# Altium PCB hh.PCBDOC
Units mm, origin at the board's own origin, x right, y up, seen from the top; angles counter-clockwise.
Board outline 200 x 200 mm, 4 copper layers (Top Layer, Internal Plane 1, Internal Plane 2, Bottom Layer); 47 components, 0 nets, 248 pads, 0 vias.
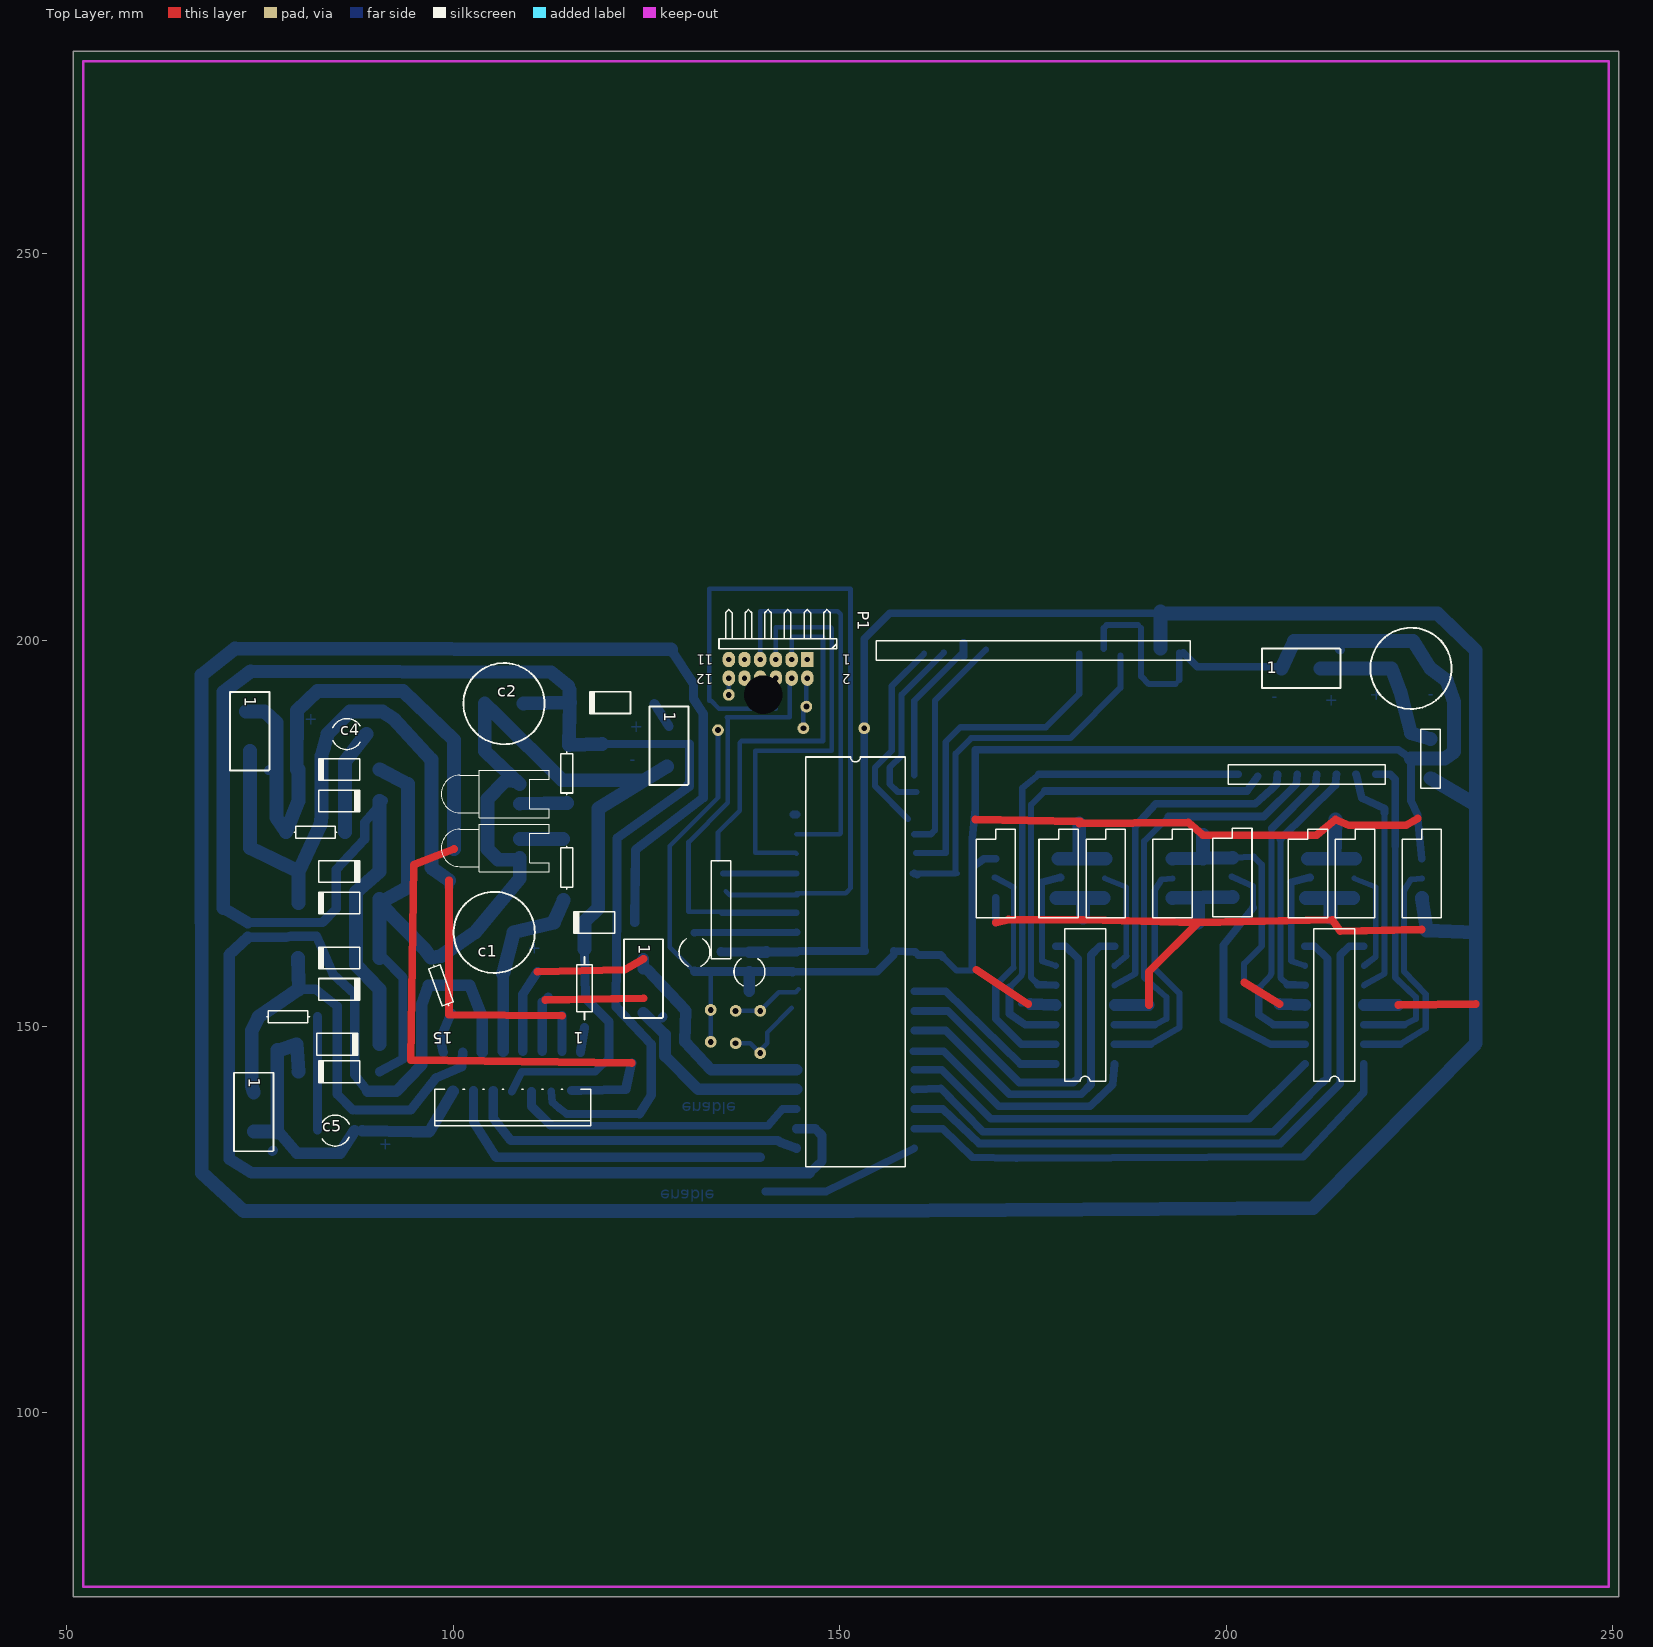
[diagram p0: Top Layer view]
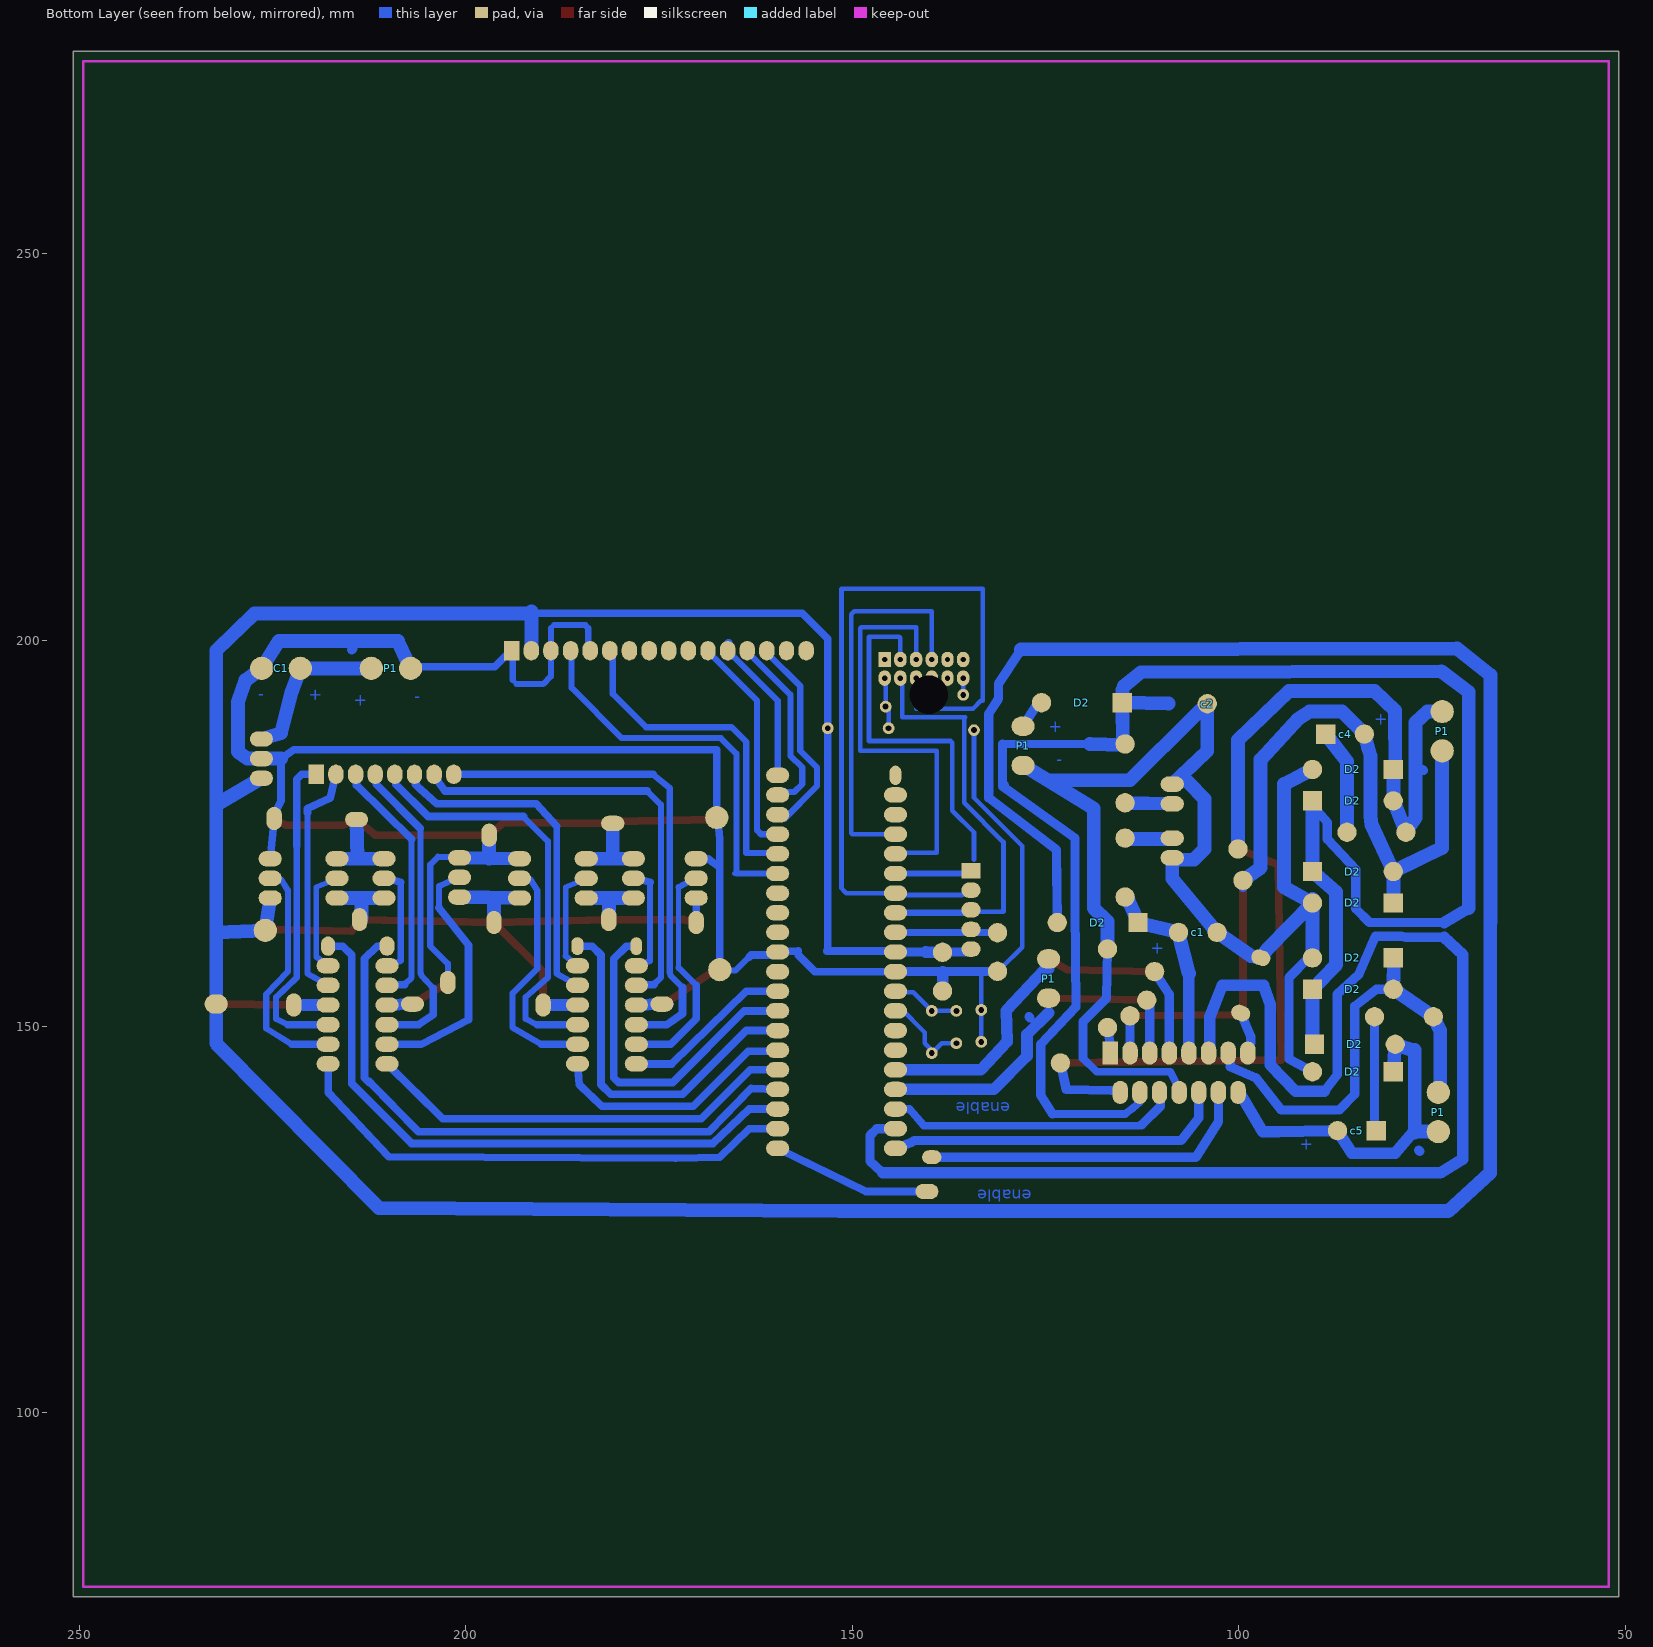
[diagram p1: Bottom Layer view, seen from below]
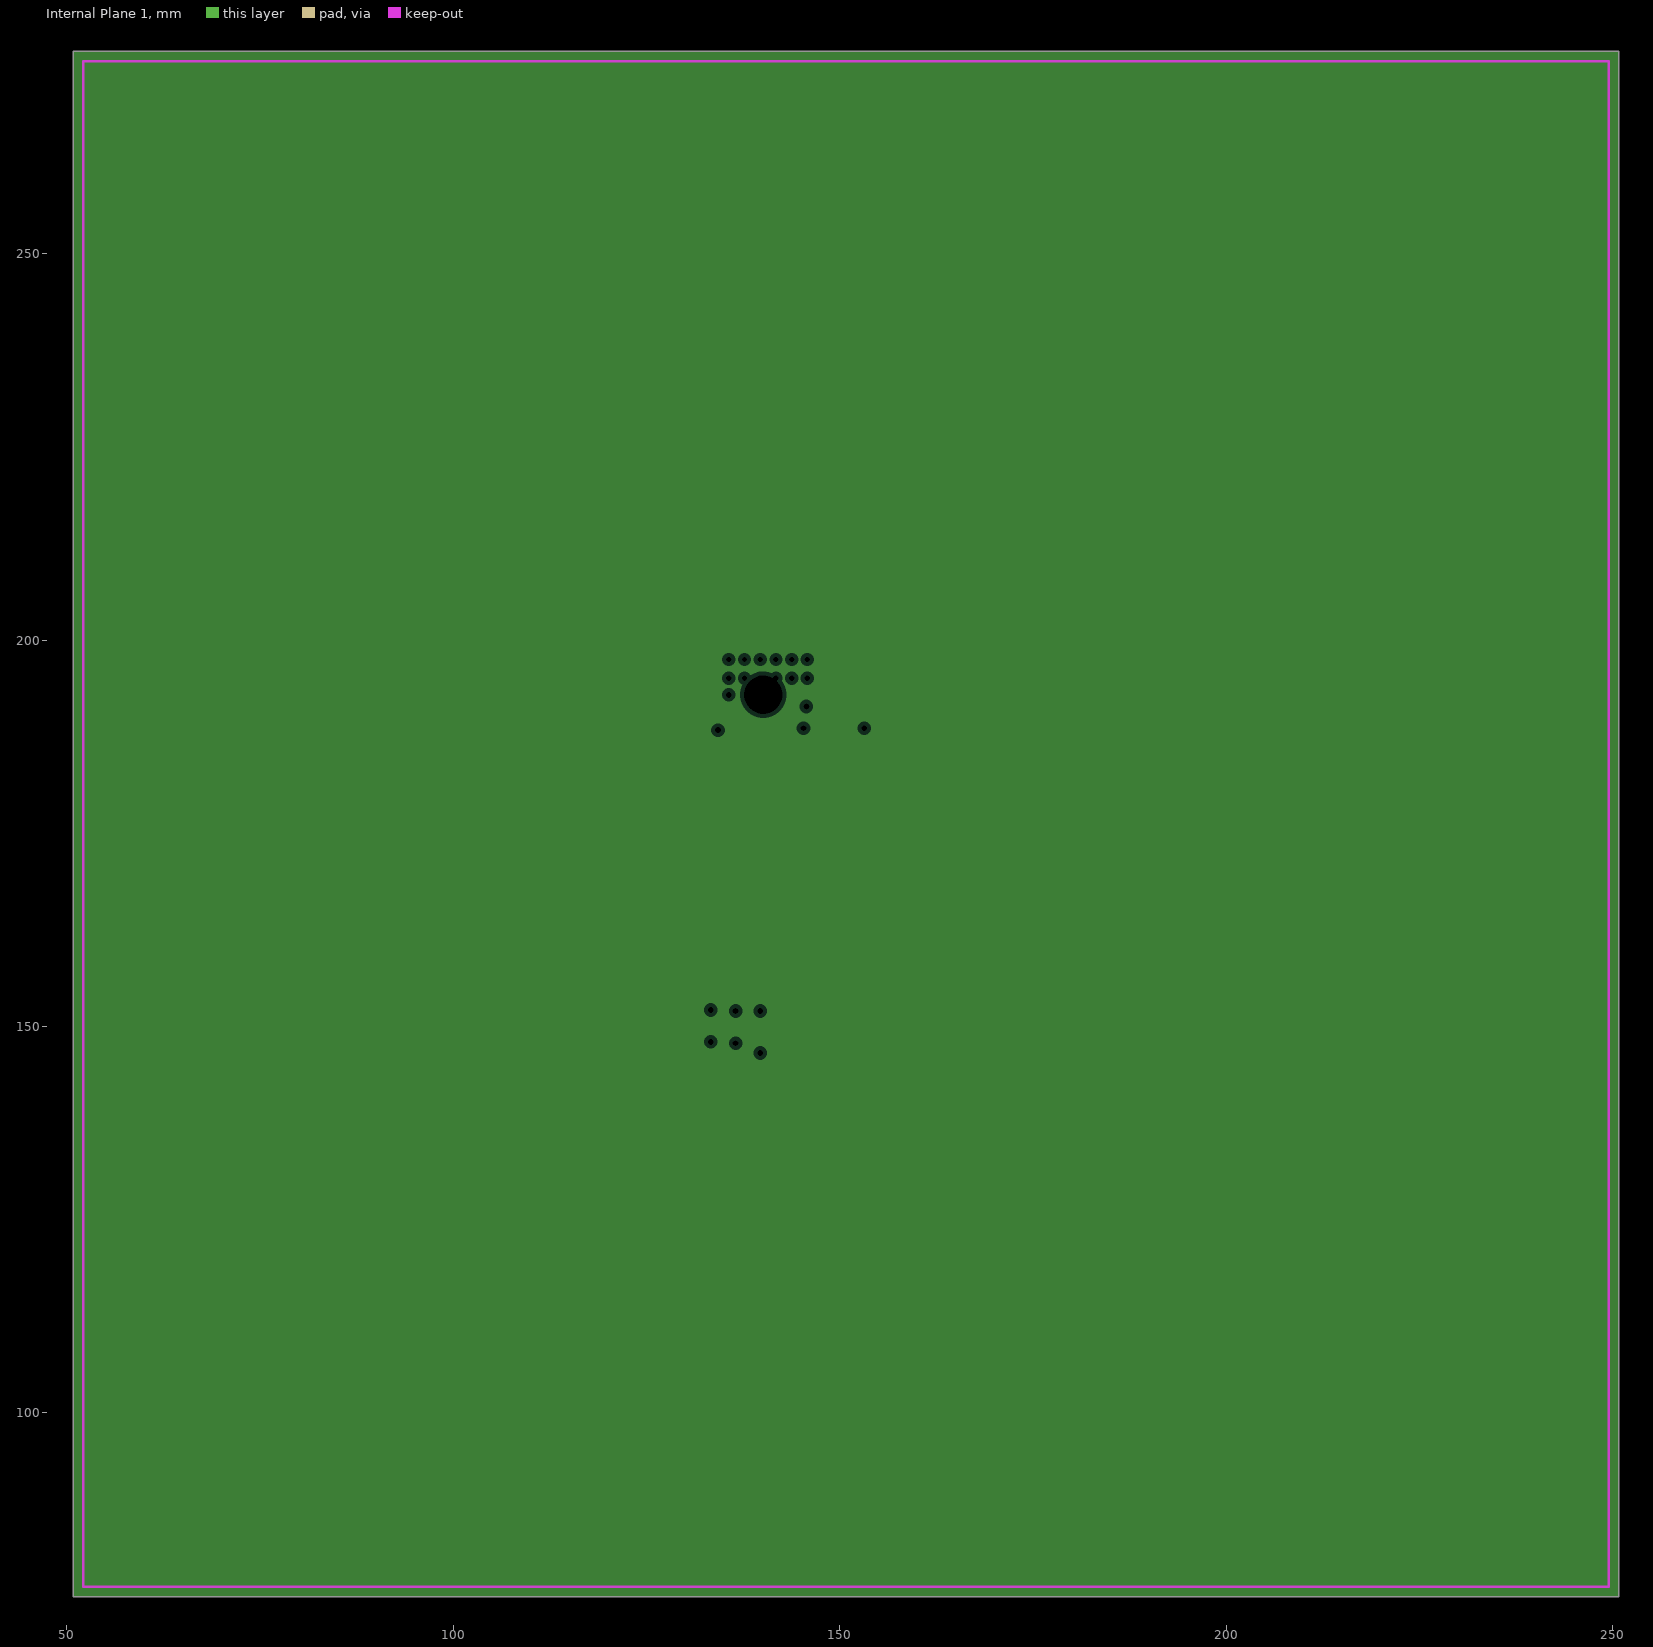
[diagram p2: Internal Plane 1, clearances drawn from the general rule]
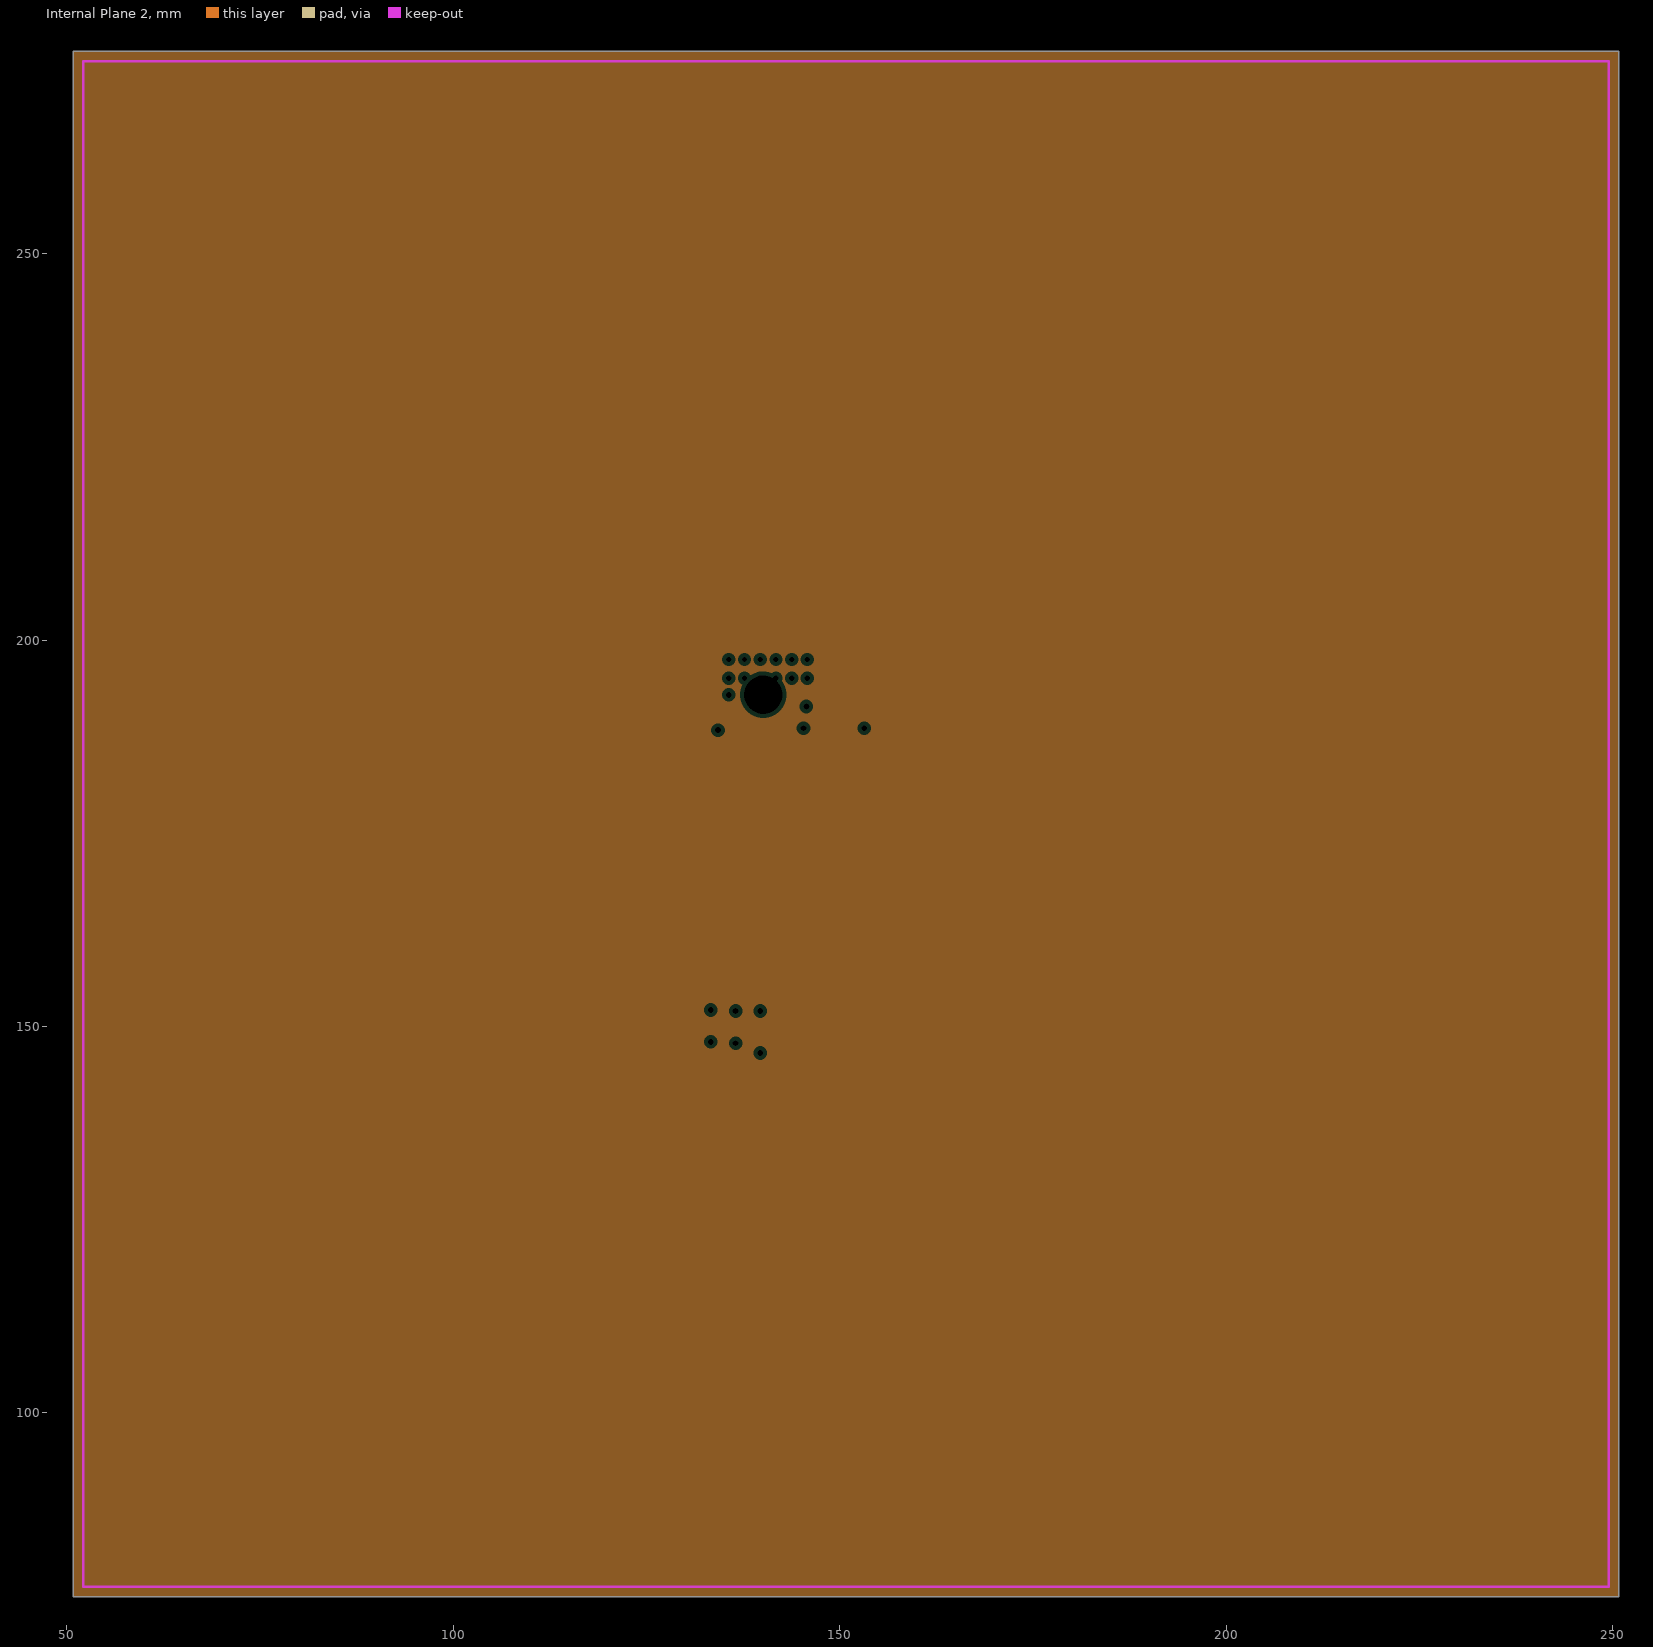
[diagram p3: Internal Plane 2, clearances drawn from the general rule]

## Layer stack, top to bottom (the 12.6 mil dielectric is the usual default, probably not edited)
Top Layer: signal copper 0.0356
Dielectric: dielectric 0.32, FR-4, Dk 4.8
Internal Plane 1: plane copper 0.0356
Dielectric: dielectric 0.32, FR-4, Dk 4.8
Internal Plane 2: plane copper 0.0356
Dielectric: dielectric 0.32, FR-4, Dk 4.8
Bottom Layer: signal copper 0.0356

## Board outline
50.8,76.2 250.8,76.2 250.8,276.2 50.8,276.2

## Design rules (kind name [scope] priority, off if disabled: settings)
Clearance [All] p1: gap=0.2
ComponentClearance [All] p1: gap=0.254 collisioncheckmode=0 verticalgap=0.254
PlaneClearance [All] p1: clearance=0.508
PlaneConnect [All] p1: planeconnectstyle=Relief reliefexpansion=0.508 reliefentries=4 reliefconductorwidth=0.254 reliefairgap=0.254
PolygonConnect [All] p1: connectstyle=Relief reliefconductorwidth=0.254 reliefentries=4 polygonreliefangle="90 Angle"
RoutingVias [All] p1: holewidth=0.3 width=1 viastyle="Through Hole" minholewidth=0.711 minwidth=1.27 maxholewidth=0.711 maxwidth=1.27
SolderMaskExpansion [All] p1: expansion=0.102
TestPointUsage [All] p1: valid=0 allowmultiple=FALSE
Testpoint [All] p1: side=15 testpointundercomponent=TRUE minsize=1.016 maxsize=2.54 preferedsize=1.524 minholesize=0 maxholesize=1.016 preferedholesize=0.813 testpointgrid=0.025 style=1023 order=0123456789
Width [All] p1: maxlimit=0.6 minlimit=0.6 preferedwidth=0.6
16 further rules are at their usual default settings.

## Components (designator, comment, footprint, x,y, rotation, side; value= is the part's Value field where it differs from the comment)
C1 "Cap Pol1" RB5-10.5#1 223.902,196.341 r180 top
c1 "Cap Pol1" RB5-10.5#2 105.284,162.178 r180 top (schematic designator C1)
c2 "Cap Pol1" RB5-10.5#3 106.554,191.769 r180 top (schematic designator C1)
c4 "Comment" CAPR5-4X5#1 86.234,187.832 r180 top
c5 "Comment" CAPR5-4X5#1 84.71,136.524 r0 top
D2 "Diode 1N4007" DO-41 85.218,144.144 r180 top
D2 "Diode 1N4007" DO-41 85.218,158.876 r180 top
D2 "Diode 1N4007" DO-41 85.218,170.052 r0 top
D2 "Diode 1N4007" DO-41 85.218,165.988 r180 top
D2 "Diode 1N4007" DO-41 85.218,154.812 r0 top
D2 "Diode 1N4007" DO-41 84.964,147.7 r0 top
D2 "Diode 1N4007" DO-41 85.218,179.196 r0 top
D2 "Diode 1N4007" DO-41 85.218,183.26 r180 top
D2 "Diode 1N4007" DO-41 120.27,191.896 r180 top
D2 "Diode 1N4007" DO-41 118.238,163.448 r180 top
P1 "v motor" header2p#1 124.588,158.749 r270 top
P1 "v motor" header2p#2 207.138,196.341 r0 top
P1 "v motor" header2p#2 73.661,190.753 r270 top
P1 "v motor" header2p#2 74.169,141.477 r270 top
P1 "v motor" header2p#1 127.89,188.848 r270 top
P1 "Header 6X2H" HDR2X6H 148.336,197.612 r180 top
? "Comment" HDR1X5 134.62,170.18 r270 top
? "Comment" VR5 225.299,169.163 r90 top
? "Comment" VR5 216.663,169.163 r90 top
? "Comment" 646-06#1 213.996,152.78 r90 top
? "Comment" VR5 200.788,169.29 r90 top
? "Comment" VR5 210.567,169.163 r90 top
? "Comment" VR5 193.041,169.163 r90 top
? "Comment" HDR1X3 226.442,182.117 r90 top
? "Comment" CAPR5-4X5#2 138.304,157.098 r270 top
? "Comment" VR5 184.405,169.163 r90 top
? "Comment" AXIAL-0.3#1 82.17,175.132 r180 top
? "Comment" AXIAL-0.3#1 78.614,151.256 r180 top
? "Comment" LED-0 108.586,173.1 r270 top
? "Comment" LED-0 108.586,180.085 r270 top
? "Comment" AXIAL-0.3#1 114.682,182.752 r270 top
? "Comment" AXIAL-0.3#1 114.682,170.56 r270 top
? "Comment" KV015 107.697,144.017 r180 top
? "Comment" AXIAL-0.3#2 98.426,155.32 r90 top
? "Comment" AXIAL-0.4 116.968,154.939 r90 top
? "Comment" CAPR5-4X5#2 131.192,159.638 r270 top
? "Comment" 646-06#2 181.738,152.78 r90 top
? "Comment" VR5 170.181,169.163 r90 top
? "Comment" VR5 178.309,169.163 r90 top
? "Comment" HDR1X16 194.056,198.628 r180 top
? "Comment" HDR1X8 219.33,182.625 r180 top
? "Comment" 40P6 152.02,158.368 r270 top

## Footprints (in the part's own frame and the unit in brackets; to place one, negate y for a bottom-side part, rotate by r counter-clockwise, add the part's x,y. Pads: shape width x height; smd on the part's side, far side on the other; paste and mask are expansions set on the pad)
40P6 [mm] "DIP; 40 Leads; Row Spacing 15.24 mm; Pitch 2.54 mm"
  oval 2.5x1.5 smd far side: 1(-24.13,-7.62)
  oval 2x3 smd far side: 2(-21.59,-7.62) 3(-19.05,-7.62) 4(-16.51,-7.62) 5(-13.97,-7.62) 6(-11.43,-7.62) 7(-8.89,-7.62) 8(-6.35,-7.62) 9(-3.81,-7.62) 10(-1.27,-7.62) 11(1.27,-7.62) 12(3.81,-7.62) 13(6.35,-7.62) 14(8.89,-7.62) 15(11.43,-7.62) 16(13.97,-7.62) 17(16.51,-7.62) 18(19.05,-7.62) 19(21.59,-7.62) 20(24.13,-7.62) 21(24.13,7.62) 22(21.59,7.62) 23(19.05,7.62) 24(16.51,7.62) 25(13.97,7.62) 26(11.43,7.62) 27(8.89,7.62) 28(6.35,7.62) 29(3.81,7.62) 30(1.27,7.62) 31(-1.27,7.62) 32(-3.81,7.62) 33(-6.35,7.62) 34(-8.89,7.62) 35(-11.43,7.62) 36(-13.97,7.62) 37(-16.51,7.62) 38(-19.05,7.62) 39(-21.59,7.62) 40(-24.13,7.62)
  silkscreen extent -26.5,-6.45 26.5,6.45
646-06#1 [mm] "DIP; 14 Leads; Row Spacing 7.62 mm; Pitch 2.54 mm"
  oval 2x3 smd far side: 1(-7.62,-3.81) 2(-5.08,-3.81) 3(-2.54,-3.81) 4(0,-3.81) 5(2.54,-3.81) 6(5.08,-3.81) 9(5.08,3.81) 10(2.54,3.81) 11(0,3.81) 12(-2.54,3.81) 13(-5.08,3.81) 14(-7.62,3.81)
  oval 2.5x1.8 smd far side: 7(7.62,-3.81)
  oval 2.5x2 smd far side: 8(7.62,3.81)
  silkscreen extent -9.85,-2.65 9.85,2.65
646-06#2 [mm] "DIP; 14 Leads; Row Spacing 7.62 mm; Pitch 2.54 mm"
  oval 2x3 smd far side: 1(-7.62,-3.81) 2(-5.08,-3.81) 3(-2.54,-3.81) 4(0,-3.81) 5(2.54,-3.81) 6(5.08,-3.81) 9(5.08,3.81) 10(2.54,3.81) 11(0,3.81) 12(-2.54,3.81) 13(-5.08,3.81) 14(-7.62,3.81)
  oval 2.3x1.6 smd far side: 7(7.62,-3.81)
  oval 2.3x1.5 smd far side: 8(7.62,3.81)
  silkscreen extent -9.85,-2.65 9.85,2.65
AXIAL-0.3#1 [mm]
  round 2.5 smd far side: 1(-3.81,0) 2(3.81,0)
  silkscreen extent -2.77,-0.76 2.77,0.76
AXIAL-0.3#2 [mm]
  oval 2x2.5 smd far side rot 20: 1(-3.58,-1.303) 2(3.58,1.303)
  silkscreen extent -2.65,-1.58 2.65,1.58
AXIAL-0.4 [mm]
  round 2.5 smd far side: 1(-5.08,0) 2(5.08,0)
  silkscreen extent -4.06,-1.02 4.06,1.02
CAPR5-4X5#1 [mm]
  rect 2.5x2.5 smd far side: 1(-2.5,0)
  round 2.5 smd far side: 2(2.5,0)
  silkscreen extent -1.69,-2 1.82,2
CAPR5-4X5#2 [mm]
  round 2.5 smd far side: 1(-2.5,0) 2(2.5,0)
  silkscreen extent -1.69,-2 1.82,2
DO-41 [mm] "Diode, Axial; Body 5.2 x 2.7 mm (LxDia. max), Lead Dia. 0.86 mm (max)"
  round 2.5 smd far side: 1(-5.23,0)
  rect 2.5x2.5 smd far side: 2(5.23,0)
  silkscreen extent -2.65,-1.41 2.75,1.4
HDR1X3 [mm] "Connector; Header; 3 Position"
  oval 2x3 smd far side: 1(0,0) 2(2.54,0) 3(5.08,0)
  silkscreen extent -1.27,-1.27 6.35,1.27
HDR1X5 [mm] "Connector; Header; 5 Position"
  rect 2x2.5 smd far side: 1(0,0)
  oval 2x2.5 smd far side: 2(2.54,0) 3(5.08,0) 4(7.62,0) 5(10.16,0)
  silkscreen extent -1.27,-1.27 11.43,1.27
HDR1X8 [mm] "Connector; Header; 8 Position"
  rect 2x2.5 smd far side: 1(0,0)
  oval 2x2.5 smd far side: 2(2.54,0) 3(5.08,0) 4(7.62,0) 5(10.16,0) 6(12.7,0) 7(15.24,0) 8(17.78,0)
  silkscreen extent -1.27,-1.27 19.05,1.27
HDR1X16 [mm] "Connector; Header; 16 Position"
  rect 2x2.5 smd far side: 1(0,0)
  oval 2x2.5 smd far side: 2(2.54,0) 3(5.08,0) 4(7.62,0) 5(10.16,0) 6(12.7,0) 7(15.24,0) 8(17.78,0) 9(20.32,0) 10(22.86,0) 11(25.4,0) 12(27.94,0) 13(30.48,0) 14(33.02,0) 15(35.56,0) 16(38.1,0)
  silkscreen extent -1.27,-1.27 39.37,1.27
HDR2X6H [mm]
  rect 1.6x2 hole 0.7: 1(2.54,0.127)
  oval 1.6x2 hole 0.7: 2(2.54,2.54) 3(4.572,0.127) 4(4.572,2.54) 5(6.604,0.127) 6(6.604,2.54) 7(8.636,0.127) 8(8.636,2.54) 9(10.668,0.127) 10(10.668,2.54) 11(12.7,0.127) 12(12.7,2.54)
  silkscreen extent -1.27,-6.35 13.97,-1.27
header2p#1 [mm]
  oval 2.5x3 smd far side: 1(0,0) 2(5.08,0)
  Bottom Layer lines w1.2: 7.62,2.413 7.493,2.54
  silkscreen extent -2.54,-2.54 7.62,2.54
header2p#2 [mm]
  round 3 smd far side: 1(0,0) 2(5.08,0)
  Bottom Layer lines w1.2: 7.493,2.54 7.62,2.413
  silkscreen extent -2.54,-2.54 7.62,2.54
KV015 [mm] "TO, Thru-Hole, Vertical, Heatsink Mounted; 15 Bent Staggered Leads; Pitch 1.27 mm"
  rect 2x3 smd far side: 1(-8.89,-2.54)
  oval 2x3 smd far side: 2(-7.62,2.54) 3(-6.35,-2.54) 4(-5.08,2.54) 5(-3.81,-2.54) 6(-2.54,2.54) 7(-1.27,-2.54) 8(0,2.54) 9(1.27,-2.54) 10(2.54,2.54) 11(3.81,-2.54) 12(5.08,2.54) 13(6.35,-2.54) 14(7.62,2.54) 15(8.89,-2.54)
  silkscreen extent -10.1,2.14 10.1,6.84
LED-0 [mm]
  oval 2x3 smd far side: 1(1.27,0) 2(-1.27,0)
  silkscreen extent -3.05,-10.16 3.05,3.81
RB5-10.5#1 [mm] "Motor, General Kind; 2 Leads"
  round 3 smd far side: 1(-2.5,0) 2(2.5,0)
  silkscreen extent -5.25,-5.25 5.25,5.25
RB5-10.5#2 [mm] "Motor, General Kind; 2 Leads"
  round 2.5 smd far side: 1(-2.5,0) 2(2.5,0)
  silkscreen extent -5.25,-5.25 5.25,5.25
RB5-10.5#3 [mm] "Motor, General Kind; 2 Leads"
  round 2.5 smd far side: 2(2.5,0)
  silkscreen extent -5.25,-5.25 5.25,5.25
VR5 [mm]
  oval 2x3 smd far side: 1(-2.54,0) 2(0,0) 3(2.54,0)
  silkscreen extent -5.08,-2.54 6.35,2.54

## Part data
C1 c1 c2: "Polarized Capacitor (Radial)"
c4 c5 ? ?: library part Cap2
D2 D2 D2 D2 D2 D2 D2 D2 D2 D2: "1 Amp General Purpose Rectifier"
P1 P1 P1 P1 P1: library part "Header 2H", "Header, 2-Pin, Right Angle"
?: library part "Header 5"
? ? ? ? ? ? ? ?: library part "RPot SM"
? ?: library part LM324N
?: library part "Header 3"
? ? ? ? ?: library part Res1
? ?: library part LED0
?: library part L298KV
?: library part Res2
?: library part "Header 16"
?: library part "Header 8"
?: library part ATmega32-16PC

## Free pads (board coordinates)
  round 2.5 smd far side: 0(99.442,168.909) 1(100.077,172.973) 2(123.064,145.287) 16(114.047,151.383) 19(110.872,157.098) 20(111.888,153.415)
  round 3 smd far side: 0(167.514,177.037) 1(225.933,162.433) 6(167.132,157.353)
  oval 2x3 smd far side: 0(189.993,152.78) 0(196.978,174.751) 0(222.251,152.78) 2(170.181,163.448) 5(181.484,163.829) 5(213.742,163.829) 6(196.343,163.448) 6(202.312,155.701) 6(224.791,176.91)
  oval 3x2.5 smd far side: 0(232.284,152.908)
  oval 3x2 smd far side: 1(174.626,152.907) 1(206.884,152.907) 2(180.976,176.275) 2(214.122,176.784) 8(140.335,128.651)
  round 1.524 hole 5: 2(140.081,192.913)
  round 1.524 hole 0.762: 3(140.081,192.913) 4(145.669,191.389) 5(145.288,188.595) 6(153.162,188.595) 7(134.239,188.341) 8(135.636,192.913) 11(133.294,152.146) 12(133.294,148.011) 13(136.525,152.019) 14(136.525,147.828) 15(139.7,152.019) 16(139.7,146.558)
  oval 2.5x1.8 smd far side: 9(139.701,133.095)

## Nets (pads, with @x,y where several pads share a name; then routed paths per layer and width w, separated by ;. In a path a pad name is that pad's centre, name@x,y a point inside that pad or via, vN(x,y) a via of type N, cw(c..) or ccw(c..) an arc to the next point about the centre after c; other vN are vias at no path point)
pads on no net: ?.1 ?.2 ?.3 ?.4 ?.5 ?.6 ?.7 ?.8 ?.9 ?.10 ?.11 ?.12 ?.13 ?.14 ?.15 ?.16 ?.17 ?.18 ?.19 ?.20 ?.21 ?.22 ?.23 ?.24 ?.25 ?.26 ?.27 ?.28 ?.29 ?.30 ?.31 ?.32 ?.33 ?.34 ?.35 ?.36 ?.37 ?.38 ?.39 ?.40 C1.1 c1.1 c1.2 C1.2 c2.2 c4.1 c4.2 c5.1 c5.2 D2.1 D2.2 P1.1 P1.2 P1.3 P1.4 P1.5 P1.6 P1.7 P1.8 P1.9 P1.10 P1.11 P1.12
copper on no net: | length 3937.4
  Top Layer w1: 99.442,168.909 99.441,151.511 114.047,151.383 ; 100.077,172.973 94.869,170.942 94.488,145.669 123.064,145.287 ; 110.872,157.098 122.174,157.353 124.588,158.749 ; 111.888,153.415 124.588,153.669 ; 167.514,176.784 181.102,176.53 180.976,176.275 195.072,176.403 196.978,174.751 211.709,174.752 214.122,176.784 215.9,176.022 223.266,176.022 224.791,176.91 ; 167.64,157.353 174.371,152.908 ; 170.181,163.448 171.831,163.83 181.484,163.829 196.343,163.448 ; 189.993,152.78 189.993,157.098 196.343,163.448 ; 202.312,155.701 206.884,152.907 ; 222.251,152.78 232.284,152.908 ; 225.299,162.559 214.757,162.306 213.742,163.829 196.343,163.448
  Bottom Layer w0.6: 76.836,136.397 77.471,137.667 77.471,141.627 ; 116.968,158.346 116.968,160.019 ; 121.032,152.526 121.286,152.018 ; 124.08,138.683 124.334,139.064 ; 130.683,157.607 128.016,160.274 128.016,173.355 134.239,179.578 134.239,188.341 ; 133.096,193.802 133.096,206.629 151.384,206.629 151.384,167.894 151.003,167.513 150.748,167.258 144.4,167.258 ; 133.096,194.056 133.096,192.151 133.35,192.151 134.366,191.135 136.398,191.135 141.732,191.135 141.732,195.072 ; 133.294,148.011 133.294,157.131 ; 134.239,171.577 134.239,175.133 137.033,177.927 137.033,186.69 137.287,186.944 147.828,186.944 147.828,200.406 143.891,200.406 143.764,200.279 143.764,197.485 ; 134.747,164.718 134.619,164.846 130.429,164.846 130.429,173.863 135.509,178.943 135.509,189.865 135.382,189.992 143.51,189.992 143.51,194.818 143.764,195.072 ; 135.255,167.513 135.763,167.005 144.526,167.005 ; 135.636,192.913 135.636,195.072 ; 136.525,147.828 138.43,147.828 139.7,146.558 139.7,146.939 140.589,147.828 140.589,149.225 143.764,152.4 ; 136.525,151.638 136.525,152.4 136.906,152.019 ; 136.525,152.019 139.7,152.019 142.113,154.432 144.272,154.432 144.653,154.813 ; 139.7,197.485 139.7,203.708 149.733,203.708 150.114,203.327 150.114,175.006 149.986,174.878 144.4,174.878 ; 140.081,192.532 140.081,194.945 ; 141.732,197.485 141.732,201.676 148.844,201.676 148.971,201.549 148.971,185.674 139.065,185.674 139.065,172.466 144.272,172.466 144.4,172.338 ; 144.399,169.801 144.401,169.799 ; 145.288,188.595 145.288,191.008 ; 145.669,195.199 145.669,191.389 ; 153.162,159.891 153.288,159.765 ; 159.766,180.34 159.893,180.34 ; 164.973,170.051 165.226,169.798 ; 173.355,152.908 174.371,152.908 ; 188.595,201.93 188.976,201.549 ; 193.421,194.31 193.929,194.818 ; 213.869,176.91 214.122,176.784 ; 226.442,182.117 226.823,182.117 ; 145.288,191.008 145.669,191.389 ; 145.288,191.008 145.669,191.389
  Bottom Layer w0.7: 172.467,157.606 172.467,165.226 172.467,168.02 ; 184.278,169.163 187.072,168.02 187.072,159.13 ; 216.536,169.163 219.33,168.02 219.329,159.004
  Bottom Layer w0.8: 116.968,160.019 117.095,158.219 ; 134.747,164.718 144.4,164.718 ; 134.874,169.798 144.4,169.798 ; 146.051,131.063 146.178,131.19 ; 158.814,176.847 154.559,181.102 154.559,183.515 156.718,185.674 156.718,194.056 160.909,198.247 ; 159.385,169.798 164.973,169.798 ; 159.64,174.878 161.797,174.878 162.306,175.387 162.306,192.151 168.91,198.755 ; 159.64,182.498 159.64,192.152 166.116,198.628 ; 159.893,172.466 163.703,172.466 163.703,186.817 165.608,188.722 176.657,188.722 180.975,193.04 180.975,198.247 ; 159.893,180.34 157.48,180.34 156.464,181.356 156.464,181.61 156.464,183.515 157.988,185.039 157.988,192.913 163.449,198.374 ; 159.894,149.478 160.148,149.478 ; 163.322,159.004 165.1,157.226 166.878,157.226 ; 164.973,170.051 164.973,185.293 167.005,187.325 179.832,187.325 186.309,193.802 186.309,197.993 ; 170.054,169.29 172.467,168.02 ; 170.181,155.32 172.467,157.606 ; 171.959,155.066 173.483,156.59 173.61,156.971 173.61,175.259 173.61,180.847 175.769,182.625 ; 175.642,155.447 174.753,156.336 174.753,160.146 174.753,173.862 174.753,177.545 174.753,178.688 176.531,180.466 ; 176.15,168.655 176.15,158.495 177.928,157.86 ; 182.5,142.493 182.5,142.874 ; 184.15,198.882 184.15,201.549 184.531,201.93 188.595,201.93 ; 185.548,155.32 188.215,156.844 188.215,174.116 188.215,175.894 ; 185.548,157.86 187.072,159.13 ; 188.976,201.549 188.976,195.326 189.992,194.31 193.421,194.31 ; 190.247,147.7 193.93,149.859 193.93,154.304 190.754,157.48 190.755,167.385 190.755,167.639 191.644,169.036 193.041,169.163 ; 190.755,150.24 192.279,151.002 192.279,153.796 189.358,156.336 189.358,157.352 189.358,172.338 189.358,173.989 192.533,177.164 ; 193.929,194.818 193.929,198.374 ; 200.661,169.417 203.455,168.147 203.455,165.353 ; 200.788,171.83 203.582,171.957 204.598,170.941 204.598,160.4 202.312,158.114 202.312,155.701 ; 204.217,154.939 205.741,156.59 205.868,156.971 205.868,172.211 205.868,175.612 ; 207.01,174.244 207.011,170.56 207.011,160.146 207.011,156.336 207.9,155.447 ; 208.408,168.655 208.408,158.495 210.186,157.86 ; 212.218,142.747 212.472,142.747 ; 214.758,142.493 214.758,142.874 ; 217.806,155.32 220.473,156.844 220.473,174.116 ; 217.806,157.86 219.329,159.004 ; 220.473,173.862 220.473,177.672 ; 221.87,173.354 221.87,172.338 221.87,157.352 221.87,156.336 224.537,153.796 224.537,151.002 223.013,150.24 ; 222.505,147.7 225.807,149.732 225.807,154.177 223.013,157.098 223.013,167.385 223.013,167.639 223.902,169.036 225.299,169.163
  Bottom Layer w1: 79.734,147.7 79.988,147.7 ; 83.694,186.028 83.734,187.832 ; 86.996,139.191 87.377,139.191 ; 104.268,191.515 104.903,191.515 ; 106.554,181.609 106.805,181.609 ; 106.932,181.482 108.586,181.355 ; 107.57,141.604 108.84,144.144 109.856,144.144 117.73,144.144 118.365,144.144 120.143,145.922 ; 112.523,137.159 140.717,137.159 142.596,139.318 144.4,139.318 ; 112.65,141.604 112.777,140.207 113.666,139.445 114.682,138.683 124.08,138.683 ; 119.254,186.562 130.557,186.562 ; 131.192,162.138 144.4,162.178 ; 140.335,128.651 148.209,128.651 159.64,134.238 ; 144.019,177.418 144.4,177.418 ; 144.4,157.098 154.814,157.098 156.973,159.257 ; 144.4,159.638 144.781,159.765 153.288,159.765 ; 153.162,159.891 153.162,200.152 156.464,203.454 191.897,203.454 ; 156.973,159.765 159.64,159.638 ; 159.513,146.811 163.45,146.811 170.579,139.682 182.373,139.699 185.294,142.493 185.548,145.16 ; 159.64,136.778 163.323,136.778 167.133,133.095 172.848,132.968 209.97,133.133 217.806,141.477 217.806,145.16 ; 159.64,139.318 163.323,139.318 168.022,134.873 170.562,134.873 207.011,134.873 214.758,142.62 ; 159.64,141.858 163.069,141.985 168.529,136.398 206.122,136.397 212.472,142.874 ; 159.64,144.398 163.196,144.398 169.546,138.048 202.947,138.048 210.186,145.16 ; 159.64,149.478 163.704,149.478 171.959,141.223 181.23,141.223 182.5,142.493 ; 159.64,152.018 163.958,152.018 173.229,142.747 180.214,142.747 180.849,143.382 180.849,143.89 180.849,158.749 179.198,160.4 177.928,160.4 ; 159.64,154.558 163.704,154.558 173.356,145.16 175.642,145.16 177.928,145.16 ; 159.64,169.798 160.021,169.671 ; 159.763,159.642 160.147,159.258 163.068,159.258 163.322,159.004 ; 165.99,197.865 165.99,199.643 ; 167.132,157.353 167.133,170.56 ; 167.514,177.037 167.514,185.674 ; 167.514,178.18 167.132,174.244 167.133,170.56 ; 167.514,185.8 222.251,185.8 223.901,184.658 223.901,179.197 224.791,177.291 ; 170.181,155.32 170.181,151.002 173.483,147.7 177.928,147.7 ; 170.181,163.448 170.181,166.623 ; 170.181,171.703 168.657,171.703 167.133,170.56 ; 171.959,155.066 171.959,151.637 173.991,150.24 177.928,150.24 ; 175.642,155.447 177.928,155.32 ; 175.769,182.625 201.55,182.625 ; 176.15,168.655 178.563,169.29 ; 176.531,180.466 202.693,180.466 204.09,182.371 ; 181.23,164.083 181.484,163.829 ; 182.5,142.874 182.5,143.89 182.5,159.257 183.643,160.4 185.548,160.4 ; 185.548,147.7 190.247,147.7 ; 185.548,150.24 190.755,150.24 ; 188.215,175.894 190.882,178.815 203.709,178.815 205.868,180.72 205.896,180.72 206.503,181.327 206.63,182.625 ; 192.533,177.164 204.852,177.164 206.884,179.196 206.912,179.196 209.043,181.327 209.17,182.625 ; 194.437,198.374 196.251,196.56 207.24,196.56 ; 203.455,165.353 199.645,160.527 199.645,155.193 199.645,150.875 205.741,147.7 210.186,147.7 ; 204.217,154.939 204.217,151.51 206.121,150.241 210.186,150.24 ; 205.868,175.612 211.583,181.327 211.71,182.625 211.583,181.609 ; 207.01,174.244 214.122,181.229 214.25,182.625 ; 207.9,155.447 210.186,155.32 ; 208.408,168.655 210.821,169.29 ; 210.186,160.4 211.456,160.4 213.107,158.749 213.107,143.89 213.107,143.382 212.472,142.747 ; 213.488,164.083 213.742,163.829 ; 214.758,142.874 214.758,143.89 214.758,159.257 215.901,160.4 217.806,160.4 ; 216.79,182.625 217.552,179.577 220.473,178.18 220.473,177.672 ; 217.806,147.7 222.505,147.7 ; 217.806,150.24 223.013,150.24 ; 219.33,182.625 221.235,182.625 221.87,181.99 221.87,181.228 221.87,173.354 ; 224.791,176.91 225.299,171.703
  Bottom Layer w1.2: 73.406,161.544 78.36,161.543 78.995,161.67 82.297,161.67 84.455,156.718 87.25,154.177 87.25,143.763 88.901,141.604 ; 73.406,163.449 83.059,163.448 84.837,165.226 84.837,170.306 88.52,174.243 88.52,176.402 90.956,179.196 ; 79.988,154.812 82.17,154.812 84.963,152.654 84.964,141.223 86.996,139.191 ; 79.988,170.052 79.988,170.56 ; 82.424,136.651 82.424,151.256 ; 87.377,139.191 94.489,139.191 97.79,143.383 101.092,144.78 101.22,146.684 ; 90.448,144.144 93.473,145.795 93.473,156.336 90.956,158.876 ; 98.68,146.684 98.426,147.954 98.426,148.716 99.729,151.74 ; 99.442,168.02 99.442,168.528 ; 99.912,141.223 100.077,141.731 ; 102.617,140.256 102.617,137.667 105.538,133.095 139.701,133.095 ; 102.617,140.55 102.617,141.731 ; 105.157,141.731 105.157,140.55 105.157,140.256 105.157,138.175 107.443,135.254 129.414,135.254 136.272,135.254 141.987,135.254 142.368,135 144.4,134.238 ; 106.805,181.609 108.586,181.355 ; 108.967,146.811 108.967,147.992 108.967,148.97 108.967,154.177 110.872,157.098 ; 110.11,141.604 110.11,139.699 112.523,137.286 ; 111.507,146.811 111.507,152.78 111.507,153.161 ; 111.888,153.415 112.269,153.796 ; 113.158,163.448 113.158,163.832 ; 114.047,146.811 114.047,151.383 ; 115.317,141.731 116.498,141.731 122.302,141.858 123.064,145.287 ; 116.46,146.684 116.968,149.859 ; 116.968,160.019 117.095,153.669 120.143,150.621 120.143,145.922 ; 121.159,165.353 121.032,152.526 125.604,147.7 125.604,141.096 124.08,138.683 ; 121.159,165.48 121.158,174.371 130.557,181.101 130.557,185.673 130.557,186.562 ; 123.468,163.448 123.571,172.847 132.334,179.578 132.334,190.481 131.064,192.405 131.064,194.329 128.143,198.755 ; 126.008,191.769 127.89,188.848 ; 131.192,157.138 143.892,157.098 ; 134.621,159.672 138.304,159.598 ; 140.463,159.638 144.4,159.638 ; 144.4,136.778 146.813,136.778 147.702,135.889 147.702,132.587 146.178,131.19
  Bottom Layer w1.5: 70.231,165.354 73.406,163.449 ; 73.406,161.544 70.993,159.258 70.994,142.62 70.993,132.842 73.914,131.064 98.679,131.064 146.051,131.063 ; 77.47,136.271 79.756,133.604 85.344,133.604 87.21,136.524 ; 88.226,136.524 94.87,136.397 96.902,136.397 99.95,141.604 ; 88.901,141.604 92.584,141.604 95.886,145.033 95.885,152.781 96.775,155.32 102.108,155.321 103.76,151.129 103.76,146.684 ; 106.427,146.811 106.427,156.844 ; 124.548,157.48 124.588,158.749 ; 124.587,151.765 127.381,148.971 127.381,146.177 131.7,141.858 139.066,141.858 ; 125.095,157.353 130.058,152.063 129.929,148.047 133.352,144.398 144.4,144.398 ; 138.304,154.598 138.304,157.098 ; 138.304,159.598 140.463,159.638 ; 138.812,141.858 144.4,141.858 ; 174.626,152.907 177.928,152.78 ; 185.548,152.78 189.993,152.78 ; 206.884,152.907 210.186,152.78 ; 217.806,152.78 222.251,152.78
  Bottom Layer w1.8: 70.231,165.354 70.231,174.371 70.231,193.294 73.787,195.961 112.649,195.834 114.808,194.056 ; 73.153,190.753 75.566,190.753 77.09,189.356 77.09,177.037 78.36,175.132 79.988,179.196 79.988,183.26 ; 73.661,185.673 73.66,173.101 79.988,170.052 ; 74.169,136.397 76.836,136.397 ; 74.169,141.477 73.915,142.366 73.914,149.479 74.804,151.256 79.988,154.812 79.884,158.876 ; 77.216,136.271 77.216,141.351 ; 77.217,141.627 77.217,146.938 ; 77.471,146.938 79.734,147.7 79.988,144.144 ; 79.734,183.26 79.757,190.88 82.424,193.42 93.473,193.42 100.077,187.07 100.077,172.973 ; 79.988,165.988 79.988,170.052 ; 85.98,175.132 85.98,184.276 88.734,187.832 ; 90.448,147.7 90.448,154.812 87.376,157.988 87.376,167.386 90.448,170.052 90.448,179.196 ; 90.448,158.876 90.448,166.496 ; 90.448,183.26 94.108,181.355 94.108,168.02 90.448,165.988 96.267,160.019 97.123,158.9 98.426,159.13 102.784,162.178 108.586,169.163 108.586,171.83 ; 99.442,168.909 97.156,170.56 97.156,184.53 92.203,189.864 90.806,190.753 86.615,190.753 83.734,187.832 82.932,185.012 82.932,177.164 82.805,176.148 79.988,170.052 ; 106.427,156.844 107.784,162.178 113.008,163.448 ; 106.554,181.609 104.395,179.45 104.395,172.973 105.792,171.576 108.586,171.576 ; 108.586,174.243 114.174,174.243 ; 108.586,178.815 114.682,178.942 ; 108.586,181.355 104.054,185.633 104.054,191.769 105.592,190.318 114.047,181.863 124.714,181.864 ; 109.094,191.769 115.063,191.896 114.936,186.435 119.254,186.562 ; 113.158,163.832 114.271,166.342 ; 115.04,191.896 115.04,193.57 ; 116.968,160.019 116.968,163.575 118.746,165.353 118.746,178.18 127.636,183.641 ; 128.143,198.755 71.756,198.881 67.437,195.453 67.438,131.063 72.898,126.111 151.639,126.11 211.201,126.492 232.284,147.827 232.284,162.178 ; 178.055,166.623 184.151,166.623 ; 178.309,171.703 184.405,171.703 ; 180.976,171.83 180.976,176.275 ; 181.484,164.083 181.484,166.623 ; 191.516,198.882 191.516,203.708 ; 191.516,203.454 205.232,203.454 ; 193.041,166.623 200.788,166.75 ; 193.041,171.703 200.788,171.83 ; 196.342,166.624 196.343,163.448 ; 196.978,171.703 196.978,174.751 ; 205.233,203.453 227.33,203.454 232.283,198.628 232.284,182.625 232.284,178.689 ; 207.138,196.341 208.788,199.898 224.155,199.898 226.402,196.341 228.473,194.818 229.49,192.023 229.489,185.547 228.22,184.657 226.442,184.657 223.901,184.658 ; 210.313,166.623 216.409,166.623 ; 210.567,171.703 216.663,171.703 ; 212.218,196.341 221.402,196.341 222.504,193.421 223.902,187.959 226.442,187.197 ; 213.488,164.083 213.488,166.623 ; 213.995,171.703 214.122,176.784 ; 225.299,166.623 225.933,162.433 232.284,162.178 ; 226.442,182.117 232.284,178.689 ; 232.284,162.686 232.284,162.178 ; 232.284,162.178 232.284,178.942 232.284,178.689

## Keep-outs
Keep-Out Layer:
  lines w0.3: 52.1,77.5 52.1,274.9 249.5,274.9 249.5,77.5 52.1,77.5

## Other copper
Bottom Layer:
  text "-" at 226.823,193.42 h1.52 r180
  text "-" at 205.868,192.023 h1.52
  text "+" at 220.092,192.023 h1.52 r90
  text "+" at 212.726,191.515 h1.52
  text "+" at 82.424,190.372 h1.52 r180
  text "+" at 122.81,188.086 h1.52
  text "-" at 122.81,183.895 h1.52
  text "+" at 111.38,160.781 h1.52 r180
  text "enable" at 129.54,140.208 h1.52 r180
  text "+" at 92.076,135.381 h1.52 r180
  text "enable" at 126.746,128.905 h1.52 r180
